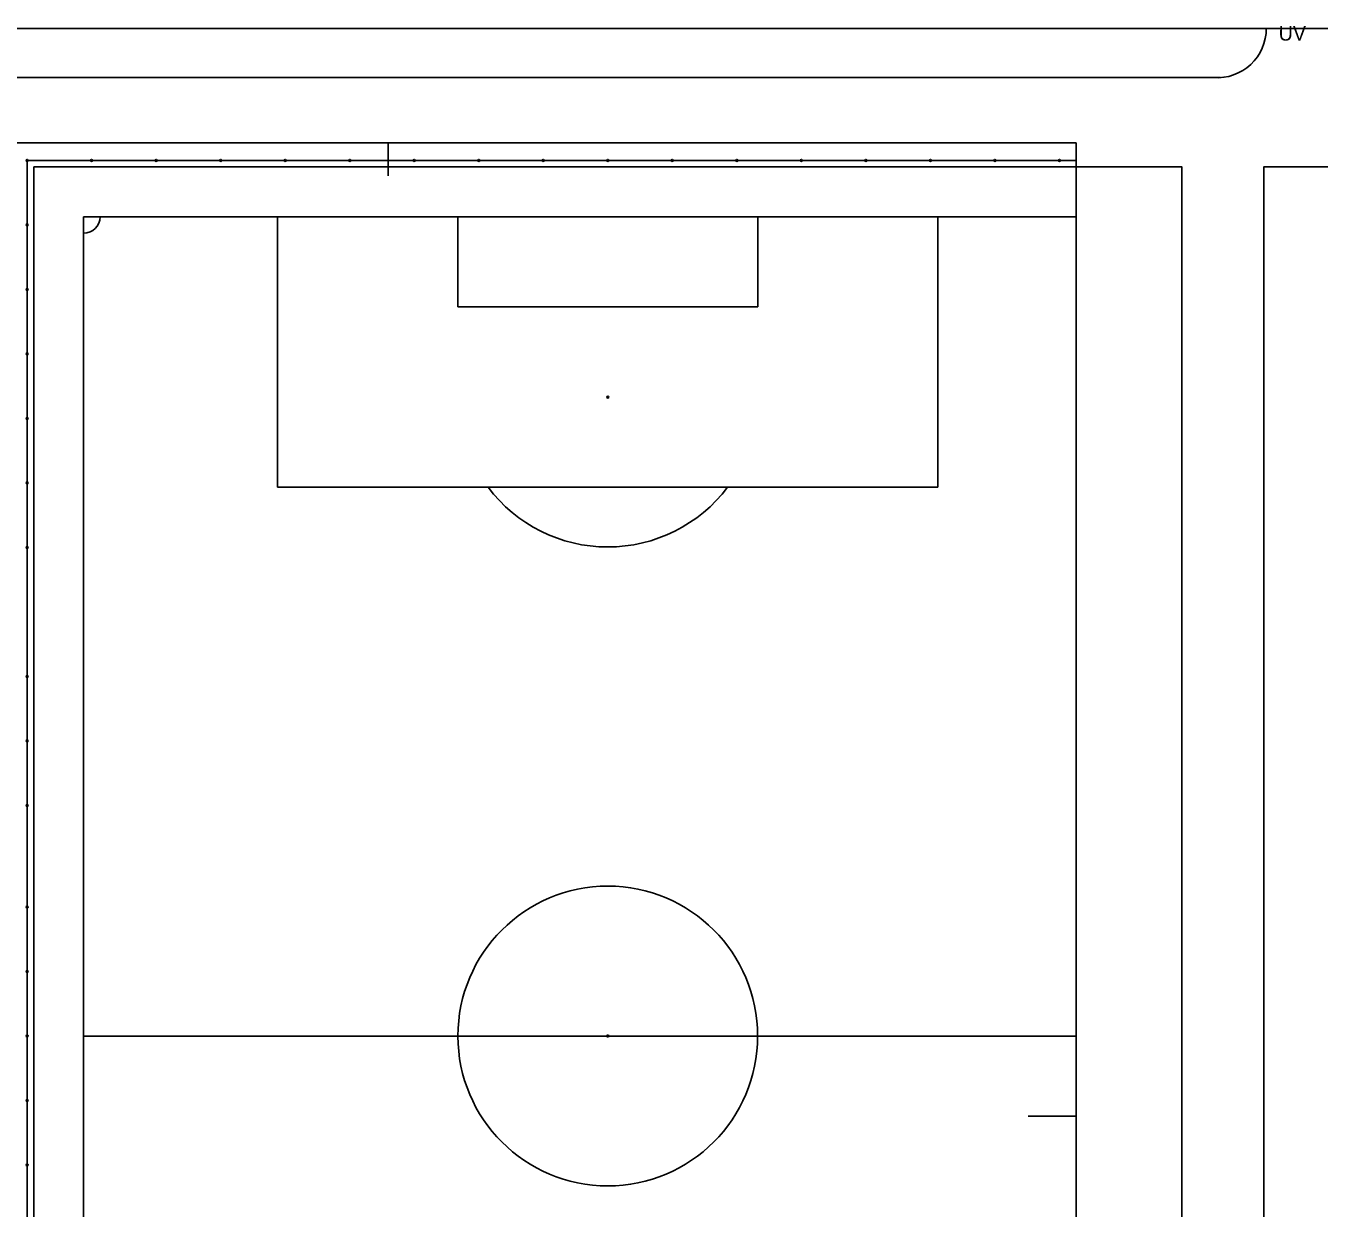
# Model space of a CAD drawing. Extents: x -264222 to -263676, y -1242344 to -1242060.
# Drawn here: x -264118.1 to -264039.2, y -1242251.5 to -1242179.3 of the extents above; entities that cross this region are included whole.
import ezdxf

# ---------------------------------------------------------------- set-up
doc = ezdxf.new("R2010")
doc.units = 0
for name, color, linetype in [('KOORDINACNA_SITUACIA_DSP', 7, 'Continuous'), ('PROJEKT_DRS_OBRUBNIKY_KOMUNIKACIE', 7, 'Continuous'), ('PROJEKT_DRS_UV_STAVBY', 7, 'Continuous'), ('RAM_NA_TLAC_8xA4_1-200', 7, 'Continuous')]:
    doc.layers.add(name, color=color, linetype=linetype)

msp = doc.modelspace()

# ---------------------------------------------------------------- linework, layer by layer
at = {"layer": 'KOORDINACNA_SITUACIA_DSP'}
for p, q in [((-264118.008, -1242187.532), (-264118.128, -1242187.532)), ((-264118.068, -1242187.592), (-264118.068, -1242187.472)), ((-264054.03, -1242187.532), (-264118.068, -1242187.532)), ((-264118.068, -1242187.532), (-264118.068, -1242294.432)), ((-264117.668, -1242294.032), (-264117.668, -1242187.932)), ((-264117.668, -1242187.932), (-264054.03, -1242187.932)), ((-264114.069, -1242187.532), (-264114.189, -1242187.532)), ((-264114.129, -1242187.592), (-264114.129, -1242187.472)), ((-264110.13, -1242187.532), (-264110.25, -1242187.532)), ((-264110.19, -1242187.592), (-264110.19, -1242187.472)), ((-264106.191, -1242187.532), (-264106.311, -1242187.532)), ((-264106.251, -1242187.592), (-264106.251, -1242187.472)), ((-264102.252, -1242187.532), (-264102.372, -1242187.532)), ((-264102.312, -1242187.592), (-264102.312, -1242187.472)), ((-264098.313, -1242187.532), (-264098.433, -1242187.532)), ((-264098.373, -1242187.592), (-264098.373, -1242187.472)), ((-264094.374, -1242187.532), (-264094.494, -1242187.532)), ((-264094.434, -1242187.592), (-264094.434, -1242187.472)), ((-264090.436, -1242187.532), (-264090.556, -1242187.532)), ((-264090.496, -1242187.592), (-264090.496, -1242187.472)), ((-264086.497, -1242187.532), (-264086.617, -1242187.532)), ((-264086.557, -1242187.592), (-264086.557, -1242187.472)), ((-264082.558, -1242187.532), (-264082.678, -1242187.532)), ((-264082.618, -1242187.592), (-264082.618, -1242187.472)), ((-264078.619, -1242187.532), (-264078.739, -1242187.532)), ((-264078.679, -1242187.592), (-264078.679, -1242187.472)), ((-264074.68, -1242187.532), (-264074.8, -1242187.532)), ((-264074.74, -1242187.592), (-264074.74, -1242187.472)), ((-264070.741, -1242187.532), (-264070.861, -1242187.532)), ((-264070.801, -1242187.592), (-264070.801, -1242187.472)), ((-264066.802, -1242187.532), (-264066.922, -1242187.532)), ((-264066.862, -1242187.592), (-264066.862, -1242187.472)), ((-264062.863, -1242187.532), (-264062.983, -1242187.532)), ((-264062.923, -1242187.592), (-264062.923, -1242187.472)), ((-264058.924, -1242187.532), (-264059.044, -1242187.532)), ((-264058.984, -1242187.592), (-264058.984, -1242187.472)), ((-264054.986, -1242187.532), (-264055.106, -1242187.532)), ((-264055.046, -1242187.592), (-264055.046, -1242187.472)), ((-264054.03, -1242190.982), (-264114.618, -1242190.982)), ((-264114.618, -1242190.982), (-264114.618, -1242290.982)), ((-264102.778, -1242207.482), (-264102.778, -1242190.982)), ((-264091.778, -1242190.982), (-264091.778, -1242196.482)), ((-264073.458, -1242196.482), (-264073.458, -1242190.982)), ((-264062.458, -1242190.982), (-264062.458, -1242207.482)), ((-264118.008, -1242191.47), (-264118.128, -1242191.47)), ((-264118.068, -1242191.41), (-264118.068, -1242191.53)), ((-264118.008, -1242195.407), (-264118.128, -1242195.407)), ((-264118.068, -1242195.347), (-264118.068, -1242195.467)), ((-264091.778, -1242196.482), (-264073.458, -1242196.482)), ((-264118.008, -1242199.345), (-264118.128, -1242199.345)), ((-264118.068, -1242199.285), (-264118.068, -1242199.405)), ((-264118.008, -1242203.282), (-264118.128, -1242203.282)), ((-264118.068, -1242203.222), (-264118.068, -1242203.342)), ((-264118.008, -1242207.22), (-264118.128, -1242207.22)), ((-264118.068, -1242207.16), (-264118.068, -1242207.28)), ((-264062.458, -1242207.482), (-264102.778, -1242207.482)), ((-264118.008, -1242211.157), (-264118.128, -1242211.157)), ((-264118.068, -1242211.097), (-264118.068, -1242211.217)), ((-264118.008, -1242219.032), (-264118.128, -1242219.032)), ((-264118.068, -1242218.972), (-264118.068, -1242219.092)), ((-264118.008, -1242222.97), (-264118.128, -1242222.97)), ((-264118.068, -1242222.91), (-264118.068, -1242223.03)), ((-264118.008, -1242226.907), (-264118.128, -1242226.907)), ((-264118.068, -1242226.847), (-264118.068, -1242226.967)), ((-264118.008, -1242233.107), (-264118.128, -1242233.107)), ((-264118.068, -1242233.047), (-264118.068, -1242233.167)), ((-264118.008, -1242237.045), (-264118.128, -1242237.045)), ((-264118.068, -1242236.985), (-264118.068, -1242237.105)), ((-264118.008, -1242240.982), (-264118.128, -1242240.982)), ((-264118.068, -1242241.042), (-264118.068, -1242240.922)), ((-264054.03, -1242240.982), (-264114.618, -1242240.982)), ((-264118.008, -1242244.92), (-264118.128, -1242244.92)), ((-264118.068, -1242244.98), (-264118.068, -1242244.86)), ((-264118.008, -1242248.857), (-264118.128, -1242248.857)), ((-264118.068, -1242248.917), (-264118.068, -1242248.797))]:
    msp.add_line(p, q, dxfattribs=at)
for centre in [(-264118.068, -1242187.532), (-264114.129, -1242187.532), (-264110.19, -1242187.532), (-264106.251, -1242187.532), (-264102.312, -1242187.532), (-264098.373, -1242187.532), (-264094.434, -1242187.532), (-264090.496, -1242187.532), (-264086.557, -1242187.532), (-264082.618, -1242187.532), (-264078.679, -1242187.532), (-264074.74, -1242187.532), (-264070.801, -1242187.532), (-264066.862, -1242187.532), (-264062.923, -1242187.532), (-264058.984, -1242187.532), (-264055.046, -1242187.532), (-264118.068, -1242191.47), (-264118.068, -1242195.407), (-264118.068, -1242199.345), (-264082.618, -1242201.982), (-264118.068, -1242203.282), (-264118.068, -1242207.22), (-264118.068, -1242211.157), (-264118.068, -1242219.032), (-264118.068, -1242222.97), (-264118.068, -1242226.907), (-264118.068, -1242233.107), (-264118.068, -1242237.045), (-264118.068, -1242240.982), (-264118.068, -1242244.92), (-264118.068, -1242248.857)]:
    msp.add_circle(centre, 0.06, dxfattribs=at)
for centre, radius, start, end in [((-264114.618, -1242190.982), 1, 270, 360), ((-264082.618, -1242201.982), 0.0303, 90, 270), ((-264082.618, -1242201.982), 0.0303, 270, 90), ((-264082.618, -1242201.982), 9.15, 216.94821, 323.05179), ((-264082.618, -1242240.982), 9.15, 360, 180), ((-264082.618, -1242240.982), 9.15, 180, 360), ((-264082.618, -1242240.982), 0.0605, 90, 270), ((-264082.618, -1242240.982), 0.0605, 270, 90)]:
    msp.add_arc(centre, radius, start, end, dxfattribs=at)
at = {"layer": 'PROJEKT_DRS_OBRUBNIKY_KOMUNIKACIE'}
for p, q in [((-263959.468, -1242179.482), (-264131.568, -1242179.482)), ((-264077.23, -1242179.482), (-264131.568, -1242179.482)), ((-264131.568, -1242179.482), (-263959.468, -1242179.482)), ((-263959.468, -1242179.482), (-264077.23, -1242179.482)), ((-264045.204, -1242182.482), (-264131.568, -1242182.482))]:
    msp.add_line(p, q, dxfattribs=at)
for points in [[(-264117.668, -1242187.932), (-264047.568, -1242187.932), (-264047.568, -1242294.032), (-264117.668, -1242294.032), (-264117.668, -1242187.932)], [(-264042.568, -1242294.032), (-263972.468, -1242294.032), (-263972.468, -1242187.932), (-264042.568, -1242187.932), (-264042.568, -1242294.032)]]:
    msp.add_lwpolyline(points, dxfattribs=at)
msp.add_arc((-264045.411, -1242179.495), 2.994, 266.03136, 0.25001, dxfattribs=at)
at = {"layer": 'RAM_NA_TLAC_8xA4_1-200'}
for p, q in [((-264096.03, -1242186.466), (-264096.03, -1242188.466)), ((-264054.03, -1242245.866), (-264056.958, -1242245.866))]:
    msp.add_line(p, q, dxfattribs=at)
msp.add_lwpolyline([(-264222.03, -1242186.466), (-264054.03, -1242186.466), (-264054.03, -1242305.266), (-264222.03, -1242305.266)], close=True, dxfattribs=at)

# ---------------------------------------------------------------- texts
at = {"layer": 'PROJEKT_DRS_UV_STAVBY'}
msp.add_text('UV', height=0.9, rotation=359.8587, dxfattribs=at).set_placement((-264041.662, -1242180.222))

doc.saveas('drawing.dxf')
